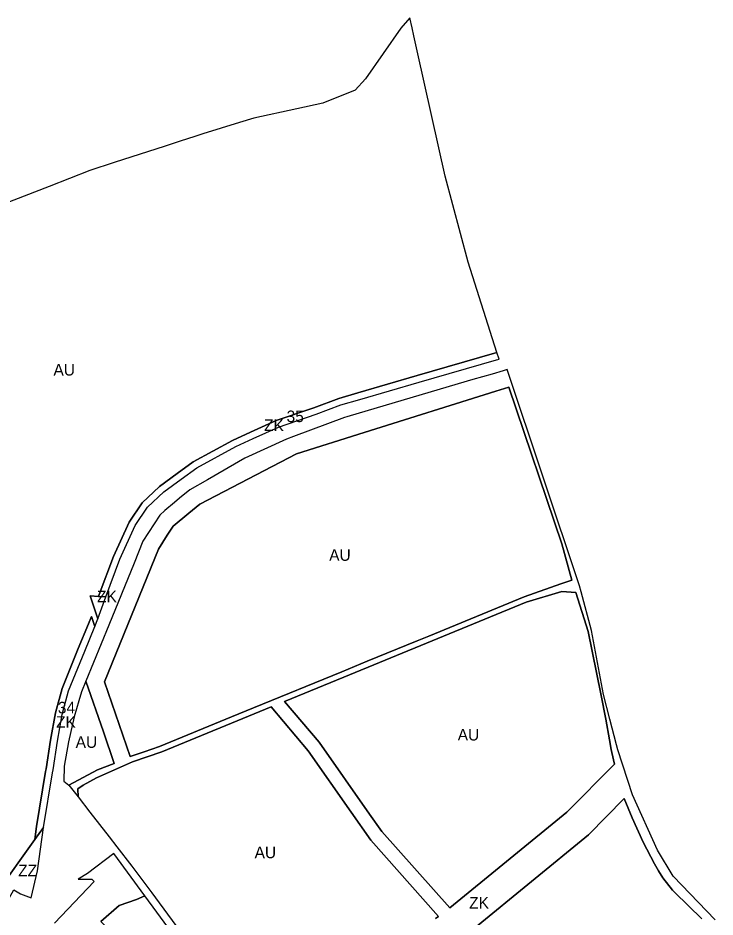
# Model space of a CAD drawing. Extents: x -522079 to -518833, y -1142398 to -1139961.
# Drawn here: x -520386 to -519784, y -1140739 to -1139961 of the extents above; entities that cross this region are included whole.
import ezdxf

# ---------------------------------------------------------------- set-up
doc = ezdxf.new("R2010")
doc.units = 0
for name, color, linetype in [('90670013', 7, 'Continuous'), ('90710013', 7, 'Continuous'), ('90710023', 7, 'Continuous'), ('90750013', 7, 'Continuous'), ('ID_navrh', 7, 'Continuous')]:
    doc.layers.add(name, color=color, linetype=linetype)

msp = doc.modelspace()

# ---------------------------------------------------------------- linework, layer by layer
at = {"layer": '90670013'}
for points in [[(-520371.84, -1140671.62), (-520371.84, -1140671.63), (-520405.96, -1140718.81), (-520399.85, -1140722.62), (-520400.9, -1140724.3), (-520396.68, -1140726.94), (-520389.9, -1140715.22), (-520384.29, -1140718.48), (-520375.15, -1140722.06), (-520369.41, -1140698.76), (-520364.42, -1140661.36), (-520371.84, -1140671.62)], [(-520314.83, -1140742.62), (-520298.98, -1140728.74), (-520284.03, -1140723.41), (-520276.72, -1140720.19), (-520303.56, -1140683.6), (-520326.31, -1140701.14), (-520334.3, -1140706.02), (-520322.69, -1140705.99), (-520320.58, -1140707.95), (-520354.98, -1140743.86)]]:
    msp.add_lwpolyline(points, dxfattribs=at)
at = {"layer": '90710013'}
for points in [[(-519783.91, -1140740.96), (-519820.17, -1140703.4), (-519833.7, -1140680.7), (-519855.18, -1140633.03), (-519867.83, -1140594.09), (-519868.98, -1140589.75), (-519874.89, -1140567.55), (-519880.22, -1140546.4), (-519890.68, -1140491.02), (-519899.47, -1140457.37), (-519901.13, -1140452.27), (-519963.47, -1140265.25), (-519967, -1140266.42), (-519976.66, -1140269.42), (-519993.22, -1140274.03), (-520037.05, -1140286.83), (-520102.1, -1140306.15), (-520104.17, -1140306.68), (-520148.17, -1140323.1), (-520154.29, -1140325.48), (-520190.37, -1140341.83), (-520222.7, -1140360.61), (-520237.84, -1140369.42), (-520246.72, -1140376.59), (-520251.21, -1140380.2), (-520259.52, -1140387.05), (-520263.92, -1140391.15), (-520278.46, -1140413.78), (-520286.11, -1140432.61), (-520307.77, -1140486.46), (-520327.66, -1140534.75), (-520312.59, -1140578.66), (-520303.27, -1140605.8), (-520317.54, -1140611.38), (-520342.44, -1140624.55), (-520334.5, -1140634.63), (-520334.77, -1140627.95), (-520330.21, -1140624.54), (-520318.61, -1140618.22), (-520287.56, -1140604.5), (-520262.2, -1140595.87), (-520167.57, -1140556.99), (-520135.55, -1140594.91), (-520098.36, -1140648.01), (-520081.44, -1140672.17), (-520022.9, -1140738.15), (-520025.44, -1140739.97)], [(-520289.45, -1140599.87), (-520311.64, -1140535.23), (-520265.09, -1140420.72), (-520257.35, -1140408.66), (-520252.32, -1140400.85), (-520238.71, -1140389.58), (-520229.31, -1140381.82), (-520145.65, -1140338.22), (-520087.13, -1140319.85), (-519973.33, -1140284.13), (-519962.19, -1140280.64), (-519916.36, -1140415.97), (-519907.62, -1140447.38), (-519917.2, -1140450.72), (-519949.02, -1140461.79), (-520031.39, -1140495.83), (-520041.44, -1140499.76), (-520084.71, -1140517.54), (-520106.55, -1140526.52), (-520182.86, -1140557.87), (-520201.76, -1140565.63), (-520263.96, -1140591.19), (-520277.29, -1140595.78), (-520289.45, -1140599.87)], [(-520310.52, -1140461.93), (-520316.75, -1140461.52), (-520324.15, -1140461.03), (-520317.28, -1140480.73), (-520310.52, -1140461.93)], [(-520104.66, -1140531.14), (-519947.24, -1140466.47), (-519916.36, -1140457.2), (-519904.17, -1140458.14), (-519893.54, -1140491.71), (-519886.24, -1140527.38), (-519882.2, -1140547.1), (-519878.23, -1140567.62), (-519875.11, -1140585.42), (-519873.69, -1140593.69), (-519873.07, -1140596.47), (-519870.83, -1140606.54), (-519911.88, -1140647.84), (-520013.2, -1140730.8), (-520072.01, -1140664.71), (-520082.56, -1140649.64), (-520126.03, -1140587.59), (-520155.91, -1140552.2), (-520104.66, -1140531.14)], [(-519893.23, -1140667.47), (-519862.3, -1140636.3), (-519855.49, -1140652.85), (-519846.13, -1140673.83), (-519836.32, -1140692.64), (-519832.73, -1140698.73), (-519829.11, -1140704.83), (-519820.55, -1140715.47), (-519818.61, -1140717.36), (-519795.23, -1140740.19)], [(-519991.87, -1140748.27), (-519893.23, -1140667.47)]]:
    msp.add_lwpolyline(points, dxfattribs=at)
at = {"layer": '90710023'}
for points in [[(-520310.52, -1140461.93), (-520298.27, -1140429.16), (-520285.01, -1140400.23), (-520274.33, -1140384.38), (-520260.24, -1140370.94), (-520245.33, -1140359.99), (-520231.71, -1140350.36), (-520198.24, -1140332), (-520183.06, -1140324.86), (-520161.16, -1140315.09), (-520128.63, -1140303.97), (-520107.24, -1140295.95), (-520091.03, -1140291.29), (-520039.59, -1140276.29), (-519972.75, -1140256.9), (-519970.54, -1140256.24), (-519972.39, -1140250.5), (-519972.61, -1140250.6), (-519974.44, -1140251.14), (-520041.27, -1140270.53), (-520092.7, -1140285.53), (-520109.13, -1140290.25), (-520130.65, -1140298.32), (-520163.36, -1140309.5), (-520185.56, -1140319.41), (-520200.96, -1140326.65), (-520234.9, -1140345.26), (-520248.84, -1140355.12), (-520264.1, -1140366.33), (-520278.94, -1140380.49), (-520290.26, -1140397.28), (-520303.81, -1140426.86), (-520316.15, -1140459.86), (-520316.75, -1140461.52), (-520310.52, -1140461.93)], [(-520371.84, -1140671.62), (-520364.42, -1140661.36), (-520356.59, -1140613.91), (-520356.14, -1140611.39), (-520352.4, -1140586.73), (-520348.21, -1140563.43), (-520342.62, -1140543.01), (-520328.73, -1140508.82), (-520319.85, -1140487.51), (-520320.44, -1140485.82), (-520322.93, -1140478.71), (-520325.43, -1140485.29), (-520334.28, -1140506.54), (-520348.31, -1140541.08), (-520354.07, -1140562.1), (-520358.32, -1140585.75), (-520362.06, -1140610.41), (-520362.5, -1140612.89), (-520370.36, -1140660.47), (-520371.84, -1140671.62)]]:
    msp.add_lwpolyline(points, dxfattribs=at)
at = {"layer": '90750013'}
for points in [[(-520371.84, -1140671.62), (-520370.36, -1140660.47), (-520362.5, -1140612.89), (-520362.06, -1140610.41), (-520358.32, -1140585.75), (-520354.07, -1140562.1), (-520348.31, -1140541.08), (-520334.28, -1140506.54), (-520325.43, -1140485.29), (-520322.93, -1140478.71), (-520320.44, -1140485.82), (-520319.85, -1140487.51), (-520317.29, -1140480.75), (-520317.28, -1140480.73), (-520324.15, -1140461.03), (-520316.75, -1140461.52), (-520316.15, -1140459.86), (-520303.81, -1140426.86), (-520290.26, -1140397.28), (-520278.94, -1140380.49), (-520264.1, -1140366.33), (-520248.84, -1140355.12), (-520234.9, -1140345.26), (-520200.96, -1140326.65), (-520185.56, -1140319.41), (-520163.36, -1140309.5), (-520130.65, -1140298.32), (-520109.13, -1140290.25), (-520092.7, -1140285.53), (-520041.27, -1140270.53), (-519974.44, -1140251.14), (-519972.61, -1140250.6), (-519972.39, -1140250.5), (-519997.42, -1140172.65), (-520017.23, -1140098.3), (-520040.68, -1139992.3), (-520044.21, -1139976.9), (-520045.81, -1139969.91), (-520047.76, -1139961.42), (-520055.62, -1139970.09), (-520085.97, -1140013.91), (-520094.95, -1140023.82), (-520123.02, -1140035.05), (-520145.26, -1140039.86), (-520182.69, -1140047.96), (-520194.98, -1140051.81), (-520226.58, -1140061.71), (-520233.47, -1140063.87), (-520246.26, -1140068.01), (-520260.01, -1140072.45), (-520288.09, -1140081.53), (-520303.34, -1140086.47), (-520324.32, -1140093.25), (-520359.48, -1140107), (-520398.93, -1140122.43)], [(-520289.45, -1140599.87), (-520277.29, -1140595.78), (-520263.96, -1140591.19), (-520201.76, -1140565.63), (-520182.86, -1140557.87), (-520106.55, -1140526.52), (-520084.71, -1140517.54), (-520041.44, -1140499.76), (-520031.39, -1140495.83), (-519949.02, -1140461.79), (-519917.2, -1140450.72), (-519907.62, -1140447.38), (-519916.36, -1140415.97), (-519962.19, -1140280.64), (-519973.33, -1140284.13), (-520087.13, -1140319.85), (-520145.65, -1140338.22), (-520229.31, -1140381.82), (-520238.71, -1140389.58), (-520252.32, -1140400.85), (-520257.35, -1140408.66), (-520265.09, -1140420.72), (-520311.64, -1140535.23), (-520289.45, -1140599.87)], [(-520104.66, -1140531.14), (-520155.91, -1140552.2), (-520126.03, -1140587.59), (-520082.56, -1140649.64), (-520072.01, -1140664.71), (-520013.2, -1140730.8), (-519911.88, -1140647.84), (-519870.83, -1140606.54), (-519873.07, -1140596.47), (-519873.69, -1140593.69), (-519875.11, -1140585.42), (-519878.23, -1140567.62), (-519882.2, -1140547.1), (-519886.24, -1140527.38), (-519893.54, -1140491.71), (-519904.17, -1140458.14), (-519916.36, -1140457.2), (-519947.24, -1140466.47), (-520104.66, -1140531.14)], [(-520346.89, -1140621.24), (-520342.44, -1140624.55), (-520317.54, -1140611.38), (-520303.27, -1140605.8), (-520312.59, -1140578.66), (-520327.66, -1140534.75), (-520331.42, -1140543.88), (-520333.94, -1140551.84), (-520337.95, -1140565.45), (-520342.68, -1140587.14), (-520346.39, -1140608.35), (-520346.89, -1140621.24)], [(-520025.44, -1140739.97), (-520022.9, -1140738.15), (-520081.44, -1140672.17), (-520098.36, -1140648.01), (-520135.55, -1140594.91), (-520167.57, -1140556.99), (-520262.2, -1140595.87), (-520287.56, -1140604.5), (-520318.61, -1140618.22), (-520330.21, -1140624.54), (-520334.77, -1140627.95), (-520334.5, -1140634.63), (-520324.2, -1140648.06), (-520307.57, -1140669.43), (-520300.9, -1140678.05), (-520287.89, -1140694.59), (-520270.86, -1140717.61)], [(-519795.23, -1140740.19), (-519818.61, -1140717.36), (-519820.55, -1140715.47), (-519829.11, -1140704.83), (-519832.73, -1140698.73), (-519836.32, -1140692.64), (-519846.13, -1140673.83), (-519855.49, -1140652.85), (-519862.3, -1140636.3), (-519893.23, -1140667.47)], [(-520405.96, -1140718.81), (-520371.84, -1140671.63), (-520371.84, -1140671.62)], [(-519893.23, -1140667.47), (-519991.87, -1140748.27)], [(-520270.86, -1140717.61), (-520267.51, -1140722.14), (-520249.86, -1140745.99)]]:
    msp.add_lwpolyline(points, dxfattribs=at)
msp.add_lwpolyline([(-520306.3, -1140797.86), (-520249.32, -1140803.75), (-520216.9, -1140807.42), (-520215.27, -1140803.99), (-520276.72, -1140720.19), (-520284.03, -1140723.41), (-520298.98, -1140728.74), (-520314.83, -1140742.62), (-520303.74, -1140753.44), (-520302.54, -1140754.92), (-520285.25, -1140776.21), (-520298.77, -1140787.91)], close=True, dxfattribs=at)

# ---------------------------------------------------------------- texts
at = {"layer": '90670013'}
msp.add_text('ZZ', height=10, dxfattribs=at).set_placement((-520386.24, -1140703.43))
at = {"layer": '90710013'}
for p in [(-520318.09, -1140466.48), (-519996.41, -1140731.28)]:
    msp.add_text('ZK', height=10, rotation=360, dxfattribs=at).set_placement(p)
at = {"layer": '90710023'}
for p in [(-520173.69, -1140318.49), (-520353.51, -1140575.02)]:
    msp.add_text('ZK', height=10, rotation=0, dxfattribs=at).set_placement(p)
at = {"layer": '90750013'}
for rotation, p in [(360, (-520355.74, -1140270.54)), (360, (-520117.4, -1140430.69)), (360, (-520006.31, -1140586.02)), (360, (-520336.56, -1140592.38)), (0, (-520181.88, -1140687.79))]:
    msp.add_text('AU', height=10, rotation=rotation, dxfattribs=at).set_placement(p)
at = {"layer": 'ID_navrh'}
for s, p in [('35', (-520154.21, -1140310.8)), ('34', (-520351.93, -1140562.59))]:
    msp.add_text(s, height=10, rotation=360, dxfattribs=at).set_placement(p)

doc.saveas('drawing.dxf')
